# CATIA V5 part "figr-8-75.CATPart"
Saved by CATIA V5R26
Part number: Part1
Bounding box of the stored display mesh (mm): x -48 to 48, y -106.879 to 0, z -32.702 to 29.91
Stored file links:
  D:\_Deepak\CATIA\CATIA V5-6R2016_Deepak\Resources\Part files\Partfiles\c08_catia_v5_6r2016_prt\figr-8-75.CATPart
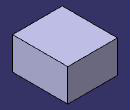
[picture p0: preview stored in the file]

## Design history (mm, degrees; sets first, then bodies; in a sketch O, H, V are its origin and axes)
Body1 (main body)
  Sketch1 on yz-plane, origin (0, 0, 0), H (0, 1, 0), V (0, 0, 1)
    line L1 (-106.8789, 29.9101) -> (0, 29.9101)
    line L2 (0, 29.9101) -> (0, -32.7018)
    line L3 (0, -32.7018) -> (-106.8789, -32.7018)
    line L4 (-106.8789, -32.7018) -> (-106.8789, 29.9101)
    point P3 (0, -32.7018)
    horizontal: L1 H, L3 H
    vertical: L2 V, L4 V
    coincidence: P3 V
  Pad1: profile Sketch1, direction (1, 0, 0), length 48, mirrored extent
Body2
  Sketch2 on yz-plane, origin (0, 0, 0), H (0, 1, 0), V (0, 0, 1)
    line L1 (30, 10) -> (90, 10)
    line L2 (90, 10) -> (90, -10)
    line L3 (90, -10) -> (30, -10)
    line L4 (30, -10) -> (30, 10)
    horizontal: L1 H, L3 H
    vertical: L2 V, L4 V
  Pad2: profile Sketch2, direction (1, 0, 0), length 26, mirrored extent
  Trim1: faces to remove face of Pad2 from Sketch2.L1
